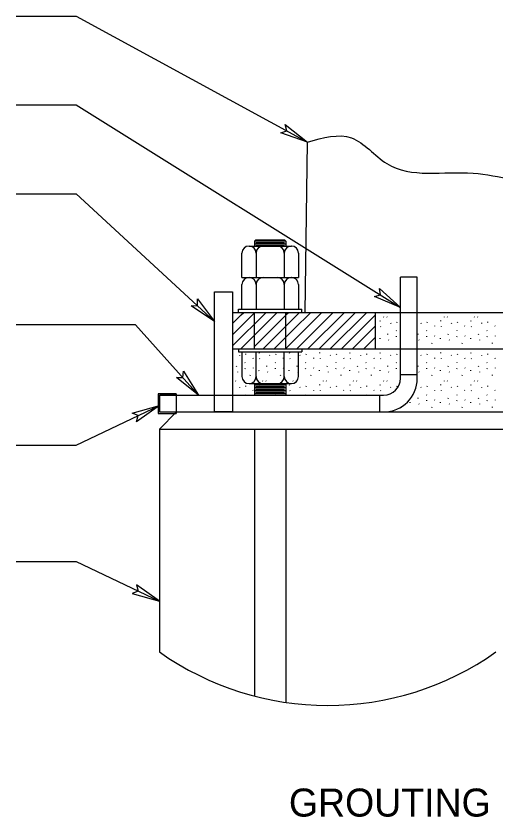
# Model space of a CAD drawing. Extents: x 99978 to 113378, y 99891 to 102182.
# Drawn here: x 111040 to 111348, y 100709 to 101224 of the extents above; entities that cross this region are included whole.
import ezdxf

# ---------------------------------------------------------------- set-up
doc = ezdxf.new("R2010")
doc.units = 0
doc.layers.add('Border Organizer Shape', color=7, linetype='Continuous')

msp = doc.modelspace()

# ---------------------------------------------------------------- linework, layer by layer
at = {"layer": 'Border Organizer Shape'}
for p, q in [((111039.96, 101223.82), (111078.64, 101223.82)), ((111078.64, 101223.82), (111227.24, 101142.84)), ((111039.96, 101166.8), (111078.64, 101166.8)), ((111078.64, 101166.8), (111287.06, 101036.56)), ((111225.88, 101033.49), (111227.24, 101142.84)), ((111194.18, 101080.15), (111193.2, 101079.18)), ((111193.2, 101079.18), (111193.2, 101076.09)), ((111213.49, 101079.18), (111193.2, 101079.18)), ((111213.49, 101077.23), (111193.2, 101077.23)), ((111194.18, 101080.15), (111212.51, 101080.15)), ((111212.51, 101078.2), (111194.18, 101078.2)), ((111213.49, 101079.18), (111212.51, 101080.15)), ((111213.49, 101079.18), (111213.49, 101076.09)), ((111189.72, 101076.09), (111216.92, 101076.09)), ((111189.72, 101076.09), (111216.97, 101076.09)), ((111212.51, 101076.26), (111194.18, 101076.26)), ((111185.21, 101055.81), (111185.21, 101071.59)), ((111194.28, 101071.59), (111194.28, 101055.81)), ((111212.41, 101071.59), (111212.41, 101055.81)), ((111221.48, 101071.59), (111221.48, 101055.81)), ((111185.21, 101055.81), (111221.48, 101055.81)), ((111185.21, 101035.52), (111185.21, 101051.3)), ((111187.62, 101055.81), (111219.07, 101055.81)), ((111189.72, 101055.81), (111216.97, 101055.81)), ((111194.28, 101051.3), (111194.28, 101035.52)), ((111212.41, 101051.3), (111212.41, 101035.52)), ((111221.48, 101051.3), (111221.48, 101035.52)), ((111297.88, 101056.11), (111287.06, 101056.11)), ((111179.13, 101033.49), (111179.13, 101033.49)), ((111179.13, 101033.49), (111179.13, 101033.49)), ((111179.13, 101033.49), (111179.13, 101033.49)), ((111179.13, 101011.93), (111200.69, 101033.49)), ((111179.13, 101033.49), (111517.82, 101033.49)), ((111179.13, 101033.49), (111179.13, 101010.06)), ((111179.13, 101026.31), (111184.76, 101031.94)), ((111183.06, 101035.52), (111223.63, 101035.52)), ((111183.06, 101033.49), (111183.06, 101035.52)), ((111183.06, 101033.49), (111223.63, 101033.49)), ((111207.88, 101033.49), (111184.44, 101010.06)), ((111184.76, 101031.94), (111186.31, 101033.49)), ((111184.76, 101031.94), (111184.76, 101031.94)), ((111185.21, 101035.52), (111221.48, 101035.52)), ((111190.39, 101030.39), (111193.2, 101033.2)), ((111215.06, 101033.49), (111193.2, 101011.64)), ((111193.2, 101010.06), (111193.2, 101033.49)), ((111198.81, 101010.06), (111222.25, 101033.49)), ((111213.49, 101031.92), (111215.06, 101033.49)), ((111213.49, 101010.06), (111213.49, 101033.49)), ((111218.56, 101022.61), (111229.44, 101033.49)), ((111220.37, 101010.06), (111243.81, 101033.49)), ((111223.63, 101033.49), (111223.63, 101035.52)), ((111224.19, 101021.06), (111236.62, 101033.49)), ((111227.56, 101010.06), (111251, 101033.49)), ((111234.75, 101010.06), (111258.19, 101033.49)), ((111241.94, 101010.06), (111265.37, 101033.49)), ((111249.12, 101010.06), (111270.76, 101031.7)), ((111270.76, 101033.49), (111270.76, 101010.06)), ((111179.13, 101019.12), (111190.39, 101030.39)), ((111190.39, 101030.39), (111190.39, 101030.39)), ((111274.05, 101027.91), (111274.2, 101028.24)), ((111276.21, 101030.62), (111276.36, 101030.41)), ((111278.29, 101030.54), (111278.44, 101030.32)), ((111280.75, 101026.65), (111280.89, 101026.43)), ((111284.84, 101027.07), (111284.98, 101027.4)), ((111300.19, 101026.65), (111300.34, 101026.43)), ((111304.28, 101027.07), (111304.43, 101027.4)), ((111312.95, 101027.91), (111313.09, 101028.24)), ((111315.1, 101030.62), (111315.25, 101030.41)), ((111317.19, 101030.54), (111317.33, 101030.32)), ((111319.64, 101026.65), (111319.78, 101026.43)), ((111323.73, 101027.07), (111323.88, 101027.4)), ((111332.39, 101027.91), (111332.54, 101028.24)), ((111334.55, 101030.62), (111334.7, 101030.41)), ((111336.63, 101030.54), (111336.78, 101030.32)), ((111339.08, 101026.65), (111339.23, 101026.43)), ((111343.18, 101027.07), (111343.32, 101027.4)), ((111116.77, 101025.51), (111039.96, 101025.46)), ((111116.77, 101025.51), (111157.27, 100980.31)), ((111206, 101010.06), (111218.56, 101022.61)), ((111213.19, 101010.06), (111224.19, 101021.06)), ((111218.56, 101022.61), (111218.56, 101022.61)), ((111224.19, 101021.06), (111224.19, 101021.06)), ((111256.31, 101010.06), (111270.76, 101024.51)), ((111274.28, 101024.34), (111274.43, 101024.12)), ((111284.35, 101021.74), (111284.5, 101021.52)), ((111303.8, 101021.74), (111303.94, 101021.52)), ((111308.85, 101024.74), (111309, 101024.52)), ((111313.17, 101024.34), (111313.32, 101024.12)), ((111323.24, 101021.74), (111323.39, 101021.52)), ((111328.3, 101024.74), (111328.44, 101024.52)), ((111332.62, 101024.34), (111332.77, 101024.12)), ((111342.69, 101021.74), (111342.84, 101021.52)), ((111347.74, 101024.74), (111347.89, 101024.52)), ((111263.5, 101010.06), (111270.76, 101017.32)), ((111273.72, 101016.87), (111273.75, 101016.54)), ((111278.92, 101019.29), (111279.06, 101019.62)), ((111279.45, 101015.9), (111279.59, 101015.68)), ((111284.47, 101017.79), (111284.62, 101018.12)), ((111298.36, 101019.29), (111298.51, 101019.62)), ((111298.89, 101015.9), (111299.04, 101015.68)), ((111303.92, 101017.79), (111304.06, 101018.12)), ((111308.99, 101018.5), (111309.14, 101018.28)), ((111312.61, 101016.87), (111312.65, 101016.54)), ((111317.81, 101019.29), (111317.95, 101019.62)), ((111318.34, 101015.9), (111318.49, 101015.68)), ((111323.36, 101017.79), (111323.51, 101018.12)), ((111328.44, 101018.5), (111328.58, 101018.28)), ((111332.06, 101016.87), (111332.09, 101016.54)), ((111337.25, 101019.29), (111337.4, 101019.62)), ((111337.79, 101015.9), (111337.93, 101015.68)), ((111342.81, 101017.79), (111342.96, 101018.12)), ((111347.88, 101018.5), (111348.03, 101018.28)), ((111270.68, 101010.06), (111270.76, 101010.14)), ((111307.24, 101013.55), (111307.39, 101013.88)), ((111326.69, 101013.55), (111326.84, 101013.88)), ((111346.14, 101013.55), (111346.28, 101013.88)), ((111179.13, 101010.06), (111270.76, 101010.06)), ((111179.13, 101010.06), (111255.11, 101010.06)), ((111181.06, 101009.97), (111181.2, 101009.77)), ((111181.2, 101009.77), (111181.21, 101009.75)), ((111183.06, 101010.06), (111223.63, 101010.06)), ((111183.06, 101010.06), (111183.06, 101008.03)), ((111183.06, 101008.03), (111223.63, 101008.03)), ((111183.51, 101006.08), (111183.66, 101005.86)), ((111185.21, 101008.03), (111185.21, 100992.25)), ((111187.61, 101006.51), (111187.75, 101006.84)), ((111194.28, 100992.25), (111194.28, 101008.03)), ((111196.27, 101007.35), (111196.42, 101007.68)), ((111198.43, 101010.06), (111198.57, 101009.84)), ((111200.51, 101009.97), (111200.66, 101009.75)), ((111202.96, 101006.08), (111203.11, 101005.86)), ((111207.05, 101006.51), (111207.2, 101006.84)), ((111212.41, 100992.25), (111212.41, 101008.03)), ((111215.72, 101007.35), (111215.86, 101007.68)), ((111217.87, 101010.06), (111218.02, 101009.84)), ((111219.96, 101009.97), (111220.1, 101009.75)), ((111221.48, 100992.25), (111221.48, 101008.03)), ((111222.41, 101006.08), (111222.55, 101005.86)), ((111223.63, 101010.06), (111223.63, 101008.03)), ((111226.5, 101006.51), (111226.64, 101006.84)), ((111235.16, 101007.35), (111235.31, 101007.68)), ((111237.32, 101010.06), (111237.47, 101009.84)), ((111239.4, 101009.97), (111239.55, 101009.75)), ((111241.85, 101006.08), (111242, 101005.86)), ((111245.94, 101006.51), (111246.09, 101006.84)), ((111254.61, 101007.35), (111254.75, 101007.68)), ((111256.77, 101010.06), (111256.91, 101009.84)), ((111258.85, 101009.97), (111258.99, 101009.75)), ((111261.3, 101006.08), (111261.45, 101005.86)), ((111265.39, 101006.51), (111265.54, 101006.84)), ((111270.76, 101010.06), (111426.19, 101010.06)), ((111274.05, 101007.35), (111274.2, 101007.68)), ((111276.21, 101010.06), (111276.36, 101009.84)), ((111278.29, 101009.97), (111278.44, 101009.75)), ((111280.75, 101006.08), (111280.89, 101005.86)), ((111284.84, 101006.51), (111284.98, 101006.84)), ((111300.19, 101006.08), (111300.34, 101005.86)), ((111304.28, 101006.51), (111304.43, 101006.84)), ((111312.95, 101007.35), (111313.09, 101007.68)), ((111315.1, 101010.06), (111315.25, 101009.84)), ((111317.19, 101009.97), (111317.33, 101009.75)), ((111319.64, 101006.08), (111319.78, 101005.86)), ((111323.73, 101006.51), (111323.88, 101006.84)), ((111332.39, 101007.35), (111332.54, 101007.68)), ((111334.55, 101010.06), (111334.7, 101009.84)), ((111336.63, 101009.97), (111336.78, 101009.75)), ((111339.08, 101006.08), (111339.23, 101005.86)), ((111343.18, 101006.51), (111343.32, 101006.84)), ((111187.12, 101001.18), (111187.27, 101000.96)), ((111192.18, 101004.17), (111192.32, 101003.95)), ((111196.5, 101003.77), (111196.64, 101003.55)), ((111206.57, 101001.18), (111206.71, 101000.96)), ((111211.62, 101004.17), (111211.77, 101003.95)), ((111215.94, 101003.77), (111216.09, 101003.55)), ((111226.01, 101001.18), (111226.16, 101000.96)), ((111231.07, 101004.17), (111231.21, 101003.95)), ((111235.39, 101003.77), (111235.53, 101003.55)), ((111245.46, 101001.18), (111245.61, 101000.96)), ((111250.51, 101004.17), (111250.66, 101003.95)), ((111254.83, 101003.77), (111254.98, 101003.55)), ((111264.91, 101001.18), (111265.05, 101000.96)), ((111269.96, 101004.17), (111270.11, 101003.95)), ((111274.28, 101003.77), (111274.43, 101003.55)), ((111284.35, 101001.18), (111284.5, 101000.96)), ((111303.8, 101001.18), (111303.94, 101000.96)), ((111308.85, 101004.17), (111309, 101003.95)), ((111313.17, 101003.77), (111313.32, 101003.55)), ((111323.24, 101001.18), (111323.39, 101000.96)), ((111328.3, 101004.17), (111328.44, 101003.95)), ((111332.62, 101003.77), (111332.77, 101003.55)), ((111342.69, 101001.18), (111342.84, 101000.96)), ((111347.74, 101004.17), (111347.89, 101003.95)), ((111181.68, 100998.72), (111181.83, 100999.05)), ((111182.22, 100995.33), (111182.36, 100995.11)), ((111187.24, 100997.22), (111187.39, 100997.55)), ((111192.31, 100997.93), (111192.46, 100997.71)), ((111195.93, 100996.3), (111195.97, 100995.97)), ((111201.13, 100998.72), (111201.28, 100999.05)), ((111201.66, 100995.33), (111201.81, 100995.11)), ((111206.69, 100997.22), (111206.83, 100997.55)), ((111211.76, 100997.93), (111211.91, 100997.71)), ((111215.38, 100996.3), (111215.41, 100995.97)), ((111220.58, 100998.72), (111220.72, 100999.05)), ((111221.11, 100995.33), (111221.26, 100995.11)), ((111226.13, 100997.22), (111226.28, 100997.55)), ((111231.21, 100997.93), (111231.35, 100997.71)), ((111234.82, 100996.3), (111234.86, 100995.97)), ((111240.02, 100998.72), (111240.17, 100999.05)), ((111240.56, 100995.33), (111240.7, 100995.11)), ((111245.58, 100997.22), (111245.73, 100997.55)), ((111250.65, 100997.93), (111250.8, 100997.71)), ((111254.27, 100996.3), (111254.31, 100995.97)), ((111259.47, 100998.72), (111259.62, 100999.05)), ((111260, 100995.33), (111260.15, 100995.11)), ((111265.03, 100997.22), (111265.17, 100997.55)), ((111270.1, 100997.93), (111270.24, 100997.71)), ((111273.72, 100996.3), (111273.75, 100995.97)), ((111278.92, 100998.72), (111279.06, 100999.05)), ((111279.45, 100995.33), (111279.59, 100995.11)), ((111284.47, 100997.22), (111284.62, 100997.55)), ((111298.36, 100998.72), (111298.51, 100999.05)), ((111298.89, 100995.33), (111299.04, 100995.11)), ((111303.92, 100997.22), (111304.06, 100997.55)), ((111308.99, 100997.93), (111309.14, 100997.71)), ((111312.61, 100996.3), (111312.65, 100995.97)), ((111317.81, 100998.72), (111317.95, 100999.05)), ((111318.34, 100995.33), (111318.49, 100995.11)), ((111323.36, 100997.22), (111323.51, 100997.55)), ((111328.44, 100997.93), (111328.58, 100997.71)), ((111332.06, 100996.3), (111332.09, 100995.97)), ((111337.25, 100998.72), (111337.4, 100999.05)), ((111337.79, 100995.33), (111337.93, 100995.11)), ((111342.81, 100997.22), (111342.96, 100997.55)), ((111347.88, 100997.93), (111348.03, 100997.71)), ((111190.57, 100992.98), (111190.71, 100993.31)), ((111210.01, 100992.98), (111210.16, 100993.31)), ((111229.46, 100992.98), (111229.61, 100993.31)), ((111248.91, 100992.98), (111249.05, 100993.31)), ((111268.35, 100992.98), (111268.5, 100993.31)), ((111287.06, 100993.67), (111297.88, 100993.67)), ((111307.24, 100992.98), (111307.39, 100993.31)), ((111326.69, 100992.98), (111326.84, 100993.31)), ((111346.14, 100992.98), (111346.28, 100993.31)), ((111181.06, 100989.41), (111181.21, 100989.19)), ((111183.51, 100985.51), (111183.66, 100985.29)), ((111187.61, 100985.94), (111187.75, 100986.27)), ((111189.72, 100987.74), (111216.97, 100987.74)), ((111193.2, 100987.74), (111193.2, 100980.31)), ((111213.49, 100986.9), (111193.2, 100986.9)), ((111213.49, 100984.95), (111193.2, 100984.95)), ((111212.52, 100985.92), (111194.18, 100985.92)), ((111196.27, 100986.78), (111196.42, 100987.11)), ((111198.43, 100989.49), (111198.57, 100989.27)), ((111200.51, 100989.41), (111200.66, 100989.19)), ((111202.96, 100985.51), (111203.11, 100985.29)), ((111207.05, 100985.94), (111207.2, 100986.27)), ((111213.49, 100987.74), (111213.49, 100980.31)), ((111215.72, 100986.78), (111215.86, 100987.11)), ((111217.87, 100989.49), (111218.02, 100989.27)), ((111219.96, 100989.41), (111220.1, 100989.19)), ((111222.41, 100985.51), (111222.55, 100985.29)), ((111226.5, 100985.94), (111226.64, 100986.27)), ((111235.16, 100986.78), (111235.31, 100987.11)), ((111237.32, 100989.49), (111237.47, 100989.27)), ((111239.4, 100989.41), (111239.55, 100989.19)), ((111241.85, 100985.51), (111242, 100985.29)), ((111245.94, 100985.94), (111246.09, 100986.27)), ((111254.61, 100986.78), (111254.75, 100987.11)), ((111256.77, 100989.49), (111256.91, 100989.27)), ((111258.85, 100989.41), (111258.99, 100989.19)), ((111261.3, 100985.51), (111261.45, 100985.29)), ((111265.39, 100985.94), (111265.54, 100986.27)), ((111274.05, 100986.78), (111274.2, 100987.11)), ((111276.21, 100989.49), (111276.36, 100989.27)), ((111278.29, 100989.41), (111278.44, 100989.19)), ((111280.75, 100985.51), (111280.89, 100985.29)), ((111284.84, 100985.94), (111284.98, 100986.27)), ((111300.19, 100985.51), (111300.34, 100985.29)), ((111304.28, 100985.94), (111304.43, 100986.27)), ((111312.95, 100986.78), (111313.09, 100987.11)), ((111315.1, 100989.49), (111315.25, 100989.27)), ((111317.19, 100989.41), (111317.33, 100989.19)), ((111319.64, 100985.51), (111319.78, 100985.29)), ((111323.73, 100985.94), (111323.88, 100986.27)), ((111332.39, 100986.78), (111332.54, 100987.11)), ((111334.55, 100989.49), (111334.7, 100989.27)), ((111336.63, 100989.41), (111336.78, 100989.19)), ((111339.08, 100985.51), (111339.23, 100985.29)), ((111343.18, 100985.94), (111343.32, 100986.27)), ((111132.13, 100969.49), (111132.13, 100980.31)), ((111142.95, 100981.21), (111142.95, 100968.59)), ((111187.12, 100980.61), (111187.27, 100980.39)), ((111192.18, 100983.6), (111192.32, 100983.38)), ((111213.49, 100983), (111193.2, 100983)), ((111213.49, 100981.06), (111193.2, 100981.06)), ((111212.52, 100983.98), (111194.18, 100983.98)), ((111212.52, 100982.03), (111194.18, 100982.03)), ((111196.5, 100983.2), (111196.64, 100982.98)), ((111206.57, 100980.61), (111206.71, 100980.39)), ((111211.62, 100983.6), (111211.77, 100983.38)), ((111215.94, 100983.2), (111216.09, 100982.98)), ((111226.01, 100980.61), (111226.16, 100980.39)), ((111231.07, 100983.6), (111231.21, 100983.38)), ((111235.39, 100983.2), (111235.53, 100982.98)), ((111245.46, 100980.61), (111245.61, 100980.39)), ((111250.51, 100983.6), (111250.66, 100983.38)), ((111254.83, 100983.2), (111254.98, 100982.98)), ((111264.91, 100980.61), (111265.05, 100980.39)), ((111269.96, 100983.6), (111270.11, 100983.38)), ((111273.7, 100980.31), (111273.7, 100969.49)), ((111274.28, 100983.2), (111274.43, 100982.98)), ((111303.8, 100980.61), (111303.94, 100980.39)), ((111308.85, 100983.6), (111309, 100983.38)), ((111313.17, 100983.2), (111313.32, 100982.98)), ((111323.24, 100980.61), (111323.39, 100980.39)), ((111328.3, 100983.6), (111328.44, 100983.38)), ((111332.62, 100983.2), (111332.77, 100982.98)), ((111342.69, 100980.61), (111342.84, 100980.39)), ((111347.74, 100983.6), (111347.89, 100983.38)), ((111293.16, 100975.74), (111293.2, 100975.41)), ((111298.36, 100978.15), (111298.51, 100978.48)), ((111298.89, 100974.77), (111299.04, 100974.55)), ((111303.92, 100976.65), (111304.06, 100976.98)), ((111308.99, 100977.36), (111309.14, 100977.14)), ((111312.61, 100975.74), (111312.65, 100975.41)), ((111317.81, 100978.15), (111317.95, 100978.48)), ((111318.34, 100974.77), (111318.49, 100974.55)), ((111323.36, 100976.65), (111323.51, 100976.98)), ((111328.44, 100977.36), (111328.58, 100977.14)), ((111332.06, 100975.74), (111332.09, 100975.41)), ((111337.25, 100978.15), (111337.4, 100978.48)), ((111337.79, 100974.77), (111337.93, 100974.55)), ((111342.81, 100976.65), (111342.96, 100976.98)), ((111347.88, 100977.36), (111348.03, 100977.14)), ((111078.64, 100948.17), (111132.13, 100973.71)), ((111143.07, 100969.49), (111132.13, 100958.55)), ((111143.07, 100969.49), (111553.88, 100969.49)), ((111179.13, 100969.49), (111517.82, 100969.49)), ((111287.8, 100972.41), (111287.94, 100972.74)), ((111307.24, 100972.41), (111307.39, 100972.74)), ((111326.69, 100972.41), (111326.84, 100972.74)), ((111346.14, 100972.41), (111346.28, 100972.74)), ((111132.13, 100958.55), (111132.13, 100815.41)), ((111132.13, 100958.55), (111564.82, 100958.55)), ((111193.2, 100958.55), (111193.2, 100787)), ((111213.49, 100958.55), (111213.49, 100782.91)), ((111039.96, 100948.17), (111078.64, 100948.17)), ((111039.96, 100873.54), (111078.64, 100873.54)), ((111078.64, 100873.55), (111132.13, 100847.98))]:
    msp.add_line(p, q, dxfattribs=at)
for points in [[(111212.98, 101154.06), (111227.24, 101142.84), (111210.08, 101148.73), (111214, 101150.05)], [(111179.13, 100969.49), (111167.64, 100969.49), (111167.64, 101046.6), (111179.13, 101046.6)], [(111273.58, 101048.71), (111287.06, 101036.56), (111270.33, 101043.58), (111274.33, 101044.64)], [(111156.63, 101042.12), (111167.64, 101027.7), (111152.49, 101037.68), (111156.62, 101037.99)], [(111147.59, 100995.66), (111157.27, 100980.31), (111143.07, 100991.61), (111147.21, 100991.54)], [(111114.68, 100968.75), (111132.13, 100973.71), (111117.3, 100963.26), (111118.53, 100967.22)], [(111114.68, 100852.96), (111132.13, 100847.98), (111117.3, 100858.44), (111118.53, 100854.48)]]:
    msp.add_lwpolyline(points, close=True, dxfattribs=at)
for points in [[(111039.96, 101109.62), (111078.64, 101109.62), (111167.64, 101027.7)], [(111287.06, 101033.49), (111287.06, 101056.11)], [(111297.88, 101033.49), (111297.88, 101056.11)], [(111287.06, 101010.06), (111287.06, 101033.49)], [(111297.88, 101010.06), (111297.88, 101033.49)], [(111287.06, 100991.13), (111287.06, 101010.06)], [(111297.88, 100991.13), (111297.88, 101010.06)], [(111142.95, 100981.21), (111131.23, 100981.21), (111131.23, 100968.59), (111142.95, 100968.59)], [(111142.95, 100980.31), (111132.13, 100980.31), (111132.13, 100969.49), (111142.95, 100969.49)], [(111132.13, 100980.31), (111167.64, 100980.31)], [(111167.64, 100980.31), (111276.25, 100980.31)], [(111132.13, 100969.49), (111264.11, 100969.49)]]:
    msp.add_lwpolyline(points, dxfattribs=at)
for centre, radius, start, end in [((111189.72, 101071.59), 4.51, 90, 180), ((111189.77, 101071.59), 4.51, 0, 90), ((111198.79, 101071.59), 4.51, 90, 180), ((111207.91, 101071.59), 4.51, 0, 90), ((111216.92, 101071.59), 4.51, 90, 180), ((111216.97, 101071.59), 4.51, 0, 90), ((111189.72, 101051.3), 4.51, 90, 180), ((111189.77, 101051.3), 4.51, 0, 90), ((111198.79, 101051.3), 4.51, 90, 180), ((111207.91, 101051.3), 4.51, 0, 90), ((111216.92, 101051.3), 4.51, 90, 180), ((111216.97, 101051.3), 4.51, 0, 90), ((111189.72, 100992.25), 4.51, 180, 270), ((111189.77, 100992.25), 4.51, 270, 0), ((111198.79, 100992.25), 4.51, 180, 270), ((111207.91, 100992.25), 4.51, 270, 0), ((111216.92, 100992.25), 4.51, 180, 270), ((111216.97, 100992.25), 4.51, 270, 0), ((111276.25, 100991.13), 10.82, 270, 360), ((111276.25, 100991.13), 21.63, 270, 360), ((111240.3, 100968.15), 187.16, 234.6933, 305.3067)]:
    msp.add_arc(centre, radius, start, end, dxfattribs=at)
msp.add_spline([(111227.24, 101142.84), (111255.66, 101145.5), (111278.24, 101129.09), (111333.74, 101122.92), (111382.99, 101116.75), (111409.66, 101127.01), (111435.16, 101147.71), (111469.85, 101142.75)], degree=3, dxfattribs=at)

# ---------------------------------------------------------------- texts
msp.add_text('GROUTING DETAIL', height=18, dxfattribs=at).set_placement((111215.36, 100709.61))

doc.saveas('drawing.dxf')
